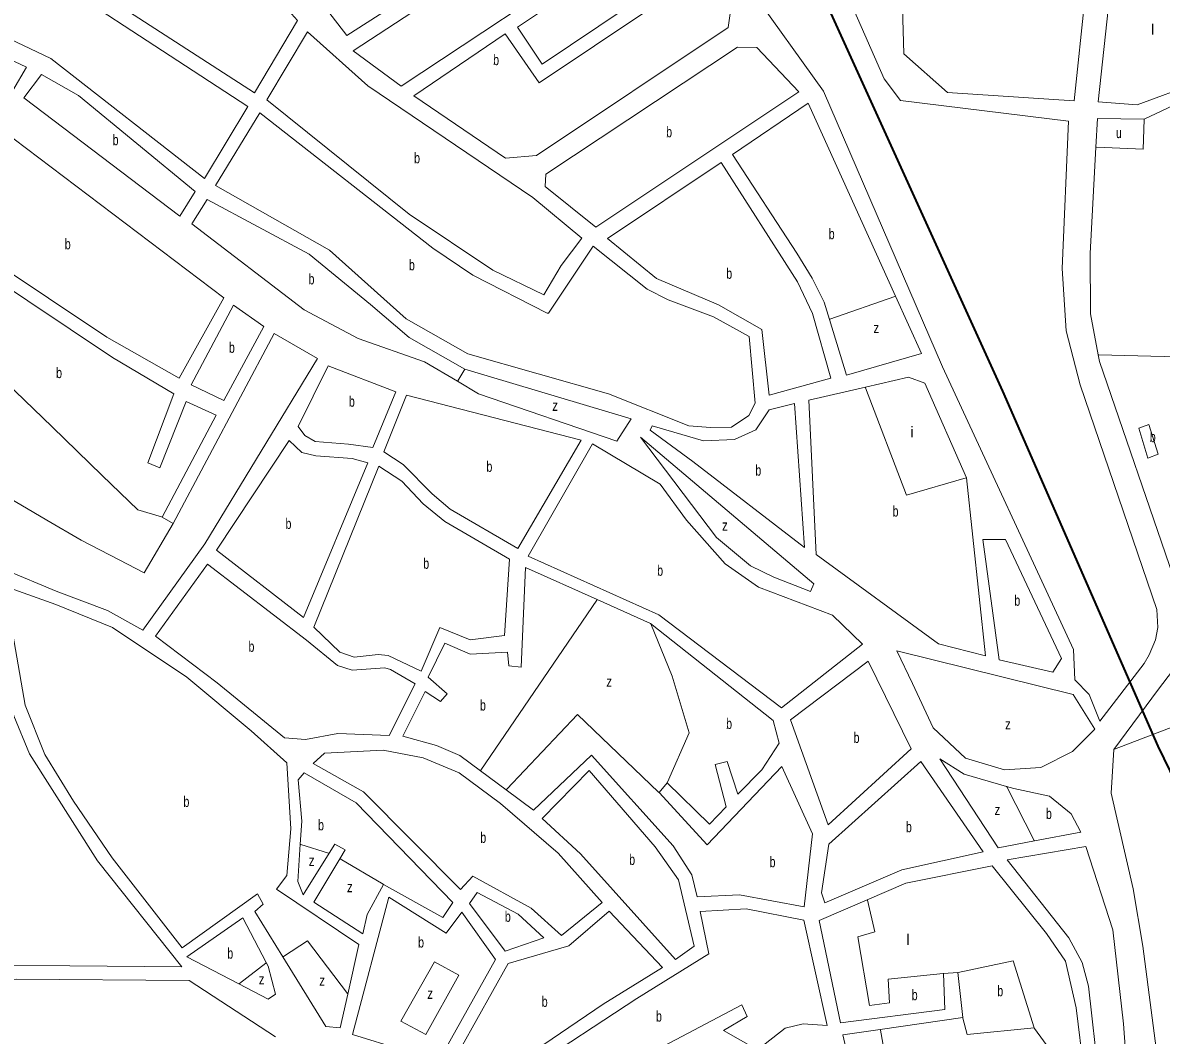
# Model space of a CAD drawing. Extents: x 639657 to 671642, y 222838 to 252123.
# Drawn here: x 648167 to 649239, y 232133 to 233086 of the extents above; entities that cross this region are included whole.
import ezdxf

# ---------------------------------------------------------------- set-up
doc = ezdxf.new("R2010")
doc.units = 0
doc.header["$LTSCALE"] = 4
for name, color, linetype, lineweight in [('1', 7, 'Continuous', 13), ('21', 7, 'Continuous', 13), ('57', 7, 'Continuous', 35)]:
    doc.layers.add(name, color=color, linetype=linetype, lineweight=lineweight)
doc.layers.add('7', color=7, linetype='Continuous')

msp = doc.modelspace()

# ---------------------------------------------------------------- linework, layer by layer
at = {"layer": '1'}
msp.add_line((648398.01, 232198), (648396.301, 232201.288), dxfattribs=at)
for points in [[(649149.42, 232796.25), (649162.7, 232745.53), (649234.9, 232533.79), (649235.74, 232517.04), (649233.58, 232505.44), (649227.55, 232491.05), (649222.82, 232482.89), (649181.25, 232428.84), (649171.15, 232453.78), (649157.62, 232467.77), (649156.35, 232496.16), (649033.16, 232762.48), (648921.04, 233022.17), (648851.52, 233119.17), (648833.54, 233184.3), (648705.42, 233567.34), (648641.96, 233707.52), (648569.71, 233868.76), (648512.26, 233999.25), (648433.24, 234174.14), (648378.3, 234266.73), (648325.37, 234321.82), (648301.67, 234334.15), (648271.66, 234336.15)], [(648410.85, 234277.57), (648411.45, 234275.57), (648414.86, 234264.21), (648539.54, 233999.64), (648604.08, 233855.17), (648722.62, 233578.92), (648824.9, 233360.7), (648844.86, 233337.47), (648978.2, 233033.69), (648993.58, 233013.129)], [(648225.054, 233203.292), (648248.4, 233188.4), (648255.07, 233200.42), (648062.83, 233327.86), (648149.35, 233433.42), (648226.41, 233333.22), (648312.95, 233263.5), (648312.48, 233220.11), (648394.74, 233169.08), (648405.91, 233157.03), (648408.65, 233107.4), (648425.61, 233088.68), (648385.14, 233020.4), (648212.53, 233132.292)], [(649177.692, 233210.382), (649156.94, 233013.02), (649037.7, 233020.93), (648996.49, 233057.3), (648995.45, 233100.91)], [(649222.88, 232995.73), (649266.95, 233016.51), (649288.86, 233018.41), (649700.501, 232988.195)], [(648835.25, 232962.36), (648906.42, 233010.59), (648988.767, 232828.86)], [(649149.42, 232796.25), (649145.61, 232855.12), (649151.76, 232993.9), (648993.58, 233013.129)], [(649179.602, 232773.657), (649172.43, 232812.33), (649172.05, 232869.05), (649177.403, 232969.313), (649178.84, 232996.23), (649222.88, 232995.73)], [(648926.536, 232807.069), (648921.49, 232823.44), (648910.34, 232845.8), (648895.97, 232869.46), (648835.25, 232962.36)], [(648326.13, 232897.12), (648340.56, 232919.89), (648436.58, 232868.61), (648494.56, 232821.24), (648530.86, 232790.03), (648583.27, 232760.29)], [(648545.23, 232767.22), (648482.93, 232789.23), (648432.02, 232816.17), (648326.13, 232897.12)], [(648988.767, 232828.86), (649013.19, 232774.96), (648942.69, 232754.66), (648926.536, 232807.069)], [(649696.519, 232781.063), (649672.36, 232773.13), (649516.76, 232732.54), (649486.67, 232722.7), (649454.65, 232710.29), (649413.37, 232686.72), (649387.35, 232664.84), (649358.11, 232634.81), (649254.42, 232501.75), (649256.81, 232531.83), (649250.18, 232565.35), (649180.76, 232767.41), (649179.602, 232773.657)], [(648583.27, 232760.29), (648739.977, 232713.536), (648726.344, 232692.457), (648596.211, 232737.095), (648576.458, 232748.767), (648545.23, 232767.22)], [(648960.414, 232743.281), (649001.01, 232752.63), (649016.48, 232747.02), (649055.72, 232657.97)], [(648914.05, 232585.72), (648907.3, 232731.05), (648960.414, 232743.281)], [(649055.72, 232657.97), (649073.63, 232490.25), (649029.16, 232501.49), (648914.05, 232585.72)], [(648707.754, 232543.291), (648640.27, 232573.4), (648636.33, 232479.66), (648624.72, 232480.96), (648623.44, 232493.65), (648588.2, 232491.76), (648564.35, 232502.11), (648548.64, 232470.09), (648566.68, 232454.59), (648560.23, 232447.28), (648545.84, 232456.55), (648524.96, 232414.64), (648556.54, 232405.78), (648578.67, 232396.51), (648598.137, 232382.016), (648622.254, 232364.061)], [(648169.29, 232443.92), (648149.82, 232555.98), (648198.16, 232538.71), (648251.66, 232516.93), (648321.69, 232470.17), (648382.05, 232419.56), (648415.76, 232389.41), (648419.37, 232327.46), (648415.69, 232283.37), (648406.01, 232270.48), (648483.55, 232218.33), (648473.05, 232171.684)], [(648879.1, 232408.15), (648873.53, 232429.24), (648758.21, 232520.78), (648707.754, 232543.291)], [(648148.401, 232478.275), (648158.54, 232433.82), (648173.55, 232397.89), (648237.53, 232297.15), (648316.77, 232197.46), (648035, 232199.74), (648013.55, 232259.79)], [(649194.31, 232402.14), (649236.25, 232458.85), (649249.595, 232476.12)], [(648411.921, 232206.703), (648385.58, 232249.43), (648393.53, 232256.52), (648387.95, 232266.2), (648317.21, 232215.1), (648251.29, 232299.93), (648214.79, 232353.32), (648187.95, 232397.44), (648169.29, 232443.92)], [(648773.77, 232370.66), (648813.71, 232331.68), (648829.41, 232348), (648818.91, 232387.8), (648830.3, 232390.59), (648840.17, 232360.03), (648862.96, 232382.8), (648879.1, 232408.15)], [(648622.254, 232364.061), (648647.83, 232345.02), (648702.67, 232396.78), (648779.32, 232311.29), (648796.92, 232283.96), (648802.06, 232263.3), (648842.03, 232265.18), (648902.62, 232253.92), (648910.62, 232322.73), (648881.87, 232386), (648811.34, 232312.11), (648766.25, 232361.42), (648773.77, 232370.66)], [(649435.192, 231967.793), (649290.77, 231943.33), (649292.43, 231931.86), (649328.02, 231936.28), (649345.19, 231853.16), (649266.36, 231847.82), (649249.9, 231999.94), (649221.67, 232216.71), (649212.68, 232270.71), (649191.78, 232361.07), (649194.31, 232402.14)], [(649085.3, 232309.38), (649030.5, 232393.21), (649053.55, 232378.67), (649093.294, 232367.255)], [(648426.5, 232373.48), (648432.09, 232379.92), (648480.85, 232351.69), (648572.12, 232258.01), (648562.44, 232243.82), (648506.8, 232274.87)], [(648428.275, 232312.776), (648429.69, 232334.55), (648426.5, 232373.48)], [(649093.294, 232367.255), (649100.17, 232365.28), (649133.9, 232358.14), (649154.3, 232341.55), (649163.18, 232324.3), (649119.701, 232315.97), (649085.3, 232309.38)], [(648455.454, 232304.409), (648430.93, 232265.29), (648426, 232277.77), (648428.275, 232312.776)], [(648465.543, 232299.222), (648470.51, 232307.61), (648460.84, 232313), (648455.454, 232304.409)], [(648506.8, 232274.87), (648491.31, 232246.71), (648487.21, 232228.43), (648441.24, 232258.18), (648465.543, 232299.222)], [(649164.269, 232079.164), (649166.15, 232099.77), (649158.89, 232158.72), (649148.82, 232202.61), (649131.01, 232228.67), (649079.7, 232292.4), (648998.47, 232276.16), (648962.185, 232260.501)], [(648962.185, 232260.501), (648917, 232241), (648936.92, 232144.6), (649035.34, 232157.16), (649034.07, 232191.15), (649047.4, 232191.99), (649052.09, 232149.61), (648974.463, 232138.318)], [(648396.301, 232201.288), (648374.4, 232243.42), (648321.5, 232206.92), (648370.508, 232181.218)], [(648473.05, 232171.684), (648465.88, 232139.83), (648452.34, 232141.14), (648411.921, 232206.703)], [(647873.27, 232058.69), (647842.52, 232171.87), (647876.67, 232179.48), (647902.85, 232191.15), (647914.22, 232197.19), (647927.75, 232198.51), (647998, 232191.36), (648045.09, 232184.46), (648160.73, 232185.61), (648323.64, 232184.54), (648405.05, 232131.52)], [(648370.508, 232181.218), (648397.98, 232166.81), (648404.87, 232171.53), (648398.01, 232198)], [(648974.463, 232138.318), (648939.28, 232133.2), (648951.326, 232079.88)]]:
    msp.add_lwpolyline(points, dxfattribs=at)
for points in [[(649287.22, 233318.98), (649213.75, 233328.11), (649179.71, 233011.91), (649216.45, 233009.06), (649272.55, 233030.03), (649362.14, 233026.03), (649369.76, 233128.72), (649279.1, 233137.23), (649274.98, 233105.01), (649261.02, 233106.53)], [(648444.58, 233110.54), (648706.86, 233280.09), (648734.76, 233242.88), (648472.26, 233074.4)], [(648000.52, 233144.9), (647974.42, 233156.59), (648019.66, 233245.64), (648064.01, 233219.58), (648130.37, 233169.87), (648379.11, 233007.52), (648338.21, 232939.88), (648193.45, 233052.89)], [(648478.05, 233060), (648523.35, 233026.84), (648715.12, 233153.75), (648746.66, 233108.58), (648801.48, 233145.24), (648741.62, 233232.56)], [(647964.35, 233144.11), (648000.93, 233125.13), (648170.66, 233044.54), (648157.74, 233022.64), (648069.45, 233078.41), (648001.8, 233105.29), (647920.77, 233131.33), (647929.3, 233156.48)], [(648632.98, 233082.33), (648712.96, 233136.14), (648736.13, 233101.3), (648656.15, 233047.49)], [(648535.37, 233017.59), (648621.37, 233075.9), (648653.34, 233029.87), (648808.56, 233134.06), (648833.45, 233097.5), (648831.07, 233082.03), (648650.91, 232961.34), (648621.69, 232959.02)], [(648491.96, 233026.92), (648435.06, 233077.92), (648396.95, 233013.94), (648530.96, 232906.09), (648609.78, 232853.54), (648657.69, 232830.27), (648673.83, 232857.76), (648693.41, 232883.73), (648647.46, 232921.84)], [(648658.83, 232932.33), (648659.7, 232943.93), (648839.86, 233063.54), (648858.13, 233063.09), (648897.83, 233021.56), (648706.49, 232893.8)], [(648168.05, 233015.75), (648184.63, 233037.86), (648219.43, 233018.05), (648329.39, 232927.64), (648314.96, 232904.45)], [(648553.07, 232874.04), (648390.28, 233001.48), (648348.52, 232933.2), (648455.71, 232872.45), (648528.08, 232807.66), (648586.07, 232774.69), (648718.42, 232736.9), (648794.04, 232706.91), (648814.45, 232705.17), (648834.43, 232705.57), (648850.56, 232716.73), (648856.59, 232728.32), (648851.06, 232791.1), (648817.34, 232809.63), (648774.59, 232825.38), (648755.04, 232835.72), (648704.15, 232876.2), (648662.18, 232813.06), (648660.89, 232813.07), (648590.87, 232848.84)], [(648356.38, 232827.45), (648135.36, 232994.3), (648068.43, 232897.04), (648136.1, 232863.85), (648246.09, 232790.41), (648314.4, 232751.84)], [(648717.65, 232883.25), (648824.5, 232954.86), (648896.37, 232842.6), (648910.74, 232812.71), (648927.87, 232751.89), (648869.84, 232735.86), (648862.81, 232797.53), (648822.01, 232820.79), (648763.6, 232845.59)], [(648308.7, 232614.9), (648403.63, 232793.85), (648444.44, 232770.15), (648338.34, 232595.73), (648280.25, 232514.52), (648246.95, 232533.06), (648198.6, 232551.18), (648150.47, 232571.24), (648130.92, 232576.86), (648100.19, 232590.87), (648076.14, 232618.43), (648045, 232647.06), (648031.05, 232673.31), (648028.29, 232712.22), (648028.99, 232785.96), (648063.9, 232882.64), (648131.58, 232851.39), (648251.66, 232771.27), (648309.23, 232737.01), (648284.67, 232671.91), (648296.27, 232667.16), (648320.83, 232729.9), (648349.19, 232716.97), (648298.17, 232620.93)], [(648393.96, 232800.31), (648365.61, 232820.56), (648325.57, 232745.37), (648356.29, 232730.72)], [(648426.33, 232706.12), (648454.54, 232763.26), (648518.34, 232738.88), (648496.81, 232686.46), (648473.6, 232689.72), (648442.44, 232692.12), (648432.77, 232697.72)], [(648507.12, 232682.36), (648528.44, 232735.65), (648692.81, 232693.29), (648633.19, 232591.47), (648569.61, 232628.32), (648552.43, 232642.74), (648525.16, 232670.3)], [(648903.1, 232592.18), (648893.76, 232727.84), (648869.69, 232721.86), (648857.21, 232703.17), (648837.22, 232693.96), (648807.99, 232692.71), (648759.65, 232706.96), (648757.72, 232702.88), (648798.09, 232673.16)], [(648820.38, 232601.54), (648748.653, 232696.177), (648911.88, 232558.2), (648908.87, 232550.89), (648874.28, 232564.27), (648852.37, 232575.05)], [(648431.34, 232526.37), (648349.51, 232589.69), (648417.94, 232693.02), (648429.97, 232681.6), (648442.86, 232678.58), (648477.24, 232675.95), (648492.07, 232672.06)], [(648881.49, 232441.27), (648957.6, 232501.16), (648929.48, 232528.5), (648859.88, 232555.04), (648828.31, 232577.02), (648792.03, 232617.91), (648767.13, 232651.92), (648703.55, 232690.05), (648643.07, 232584.14), (648765.95, 232528.72)], [(648441.01, 232517.11), (648502.38, 232668.82), (648523.86, 232654.82), (648544.04, 232633.51), (648564.45, 232616.71), (648625.45, 232581.37), (648620.66, 232509.35), (648588.21, 232505.31), (648559.85, 232516.96), (648542.2, 232475.69), (648511.05, 232490.57), (648501.81, 232491.44), (648479.02, 232489.11), (648465.49, 232493.86)], [(649086.3, 232486.36), (649071.14, 232599.91), (649092.41, 232599.88), (649145.17, 232487.79), (649136.78, 232474.9)], [(648292.06, 232508.92), (648341.12, 232576.59), (648434.12, 232505.08), (648463.33, 232481.17), (648477.3, 232476.64), (648507.81, 232478.96), (648513.4, 232477.45), (648536.6, 232463.87), (648512.06, 232415.3), (648463.71, 232417.09), (648433.4, 232411.54), (648413.42, 232413.07), (648350.06, 232464.76)], [(649004.63, 232464.33), (648990.083, 232494.986), (649155.89, 232453.8), (649176.44, 232421.04), (649155.42, 232400.04), (649125.54, 232385.24), (649091.37, 232382.92), (649054.64, 232393.73), (649024.37, 232422.37)], [(648925.45, 232331.1), (648889.86, 232430.07), (648963.18, 232485.24), (649003.51, 232402.61)], [(648671.22, 232304.55), (648712.45, 232258.04), (648674.18, 232226.9), (648645.61, 232252.53), (648590.84, 232282.72), (648579.22, 232270.26), (648487.74, 232362.22), (648440.48, 232388.94), (648451.02, 232398.61), (648506.25, 232401.33), (648544.07, 232394.19), (648577.8, 232379.95), (648616.89, 232351.08)], [(649012.74, 232390.77), (649071.33, 232305.74), (648994.61, 232288.64), (648922.17, 232257.55), (648918.96, 232267.02), (648925.87, 232312.82)], [(648762.56, 232310.24), (648700.29, 232382.37), (648656.2, 232337.05), (648692.07, 232303.88), (648781.6, 232204.39), (648799.23, 232216.84), (648784.45, 232279.24)], [(649232.038, 231829.653), (649214.54, 231993.69), (649203.35, 232143.82), (649193.32, 232232.24), (649167.98, 232310.59), (649093.89, 232298.19), (649152.06, 232224.77), (649164.5, 232201.52), (649170.5, 232179.14), (649180.11, 232092.44), (649175.15, 232064.48), (649162.26, 231969.89), (649154.98, 231825.2)], [(648633.57, 232246.96), (648594.91, 232267.44), (648587.59, 232257.13), (648621.3, 232212.13), (648657.63, 232224.56)], [(648477.48, 232133.79), (648511.74, 232262.82), (648565.65, 232229.19), (648580.5, 232248.75), (648612.05, 232204.18), (648554.39, 232100.99), (648524.32, 232119.1)], [(648681.26, 232217), (648719.32, 232249.64), (648769.35, 232196.88), (648713.67, 232162.1), (648633.26, 232107.56), (648601.22, 232069.74), (648565.13, 232094.96), (648624.09, 232200.51)], [(648812.98, 232209.51), (648804.84, 232249.32), (648848.04, 232252.06), (648902.61, 232241.44), (648924.46, 232142.04), (648901.68, 232143.79), (648884.92, 232139.72), (648858.9, 232119.32), (648826.9, 232137.43), (648849.25, 232150.74), (648844.11, 232161.5), (648669.13, 232069.22), (648641.17, 232039.57), (648611.1, 232062.84), (648642.07, 232099.59), (648745.26, 232167.65)]]:
    msp.add_lwpolyline(points, close=True, dxfattribs=at)
at = {"layer": '21'}
for points in [[(649222.88, 232995.73), (649222.865, 232995.23), (649222.013, 232967.285), (649177.903, 232969.29), (649177.403, 232969.313)], [(648926.536, 232807.069), (648927.036, 232807.244), (648988.267, 232828.685), (648988.767, 232828.86)], [(649697.531, 232833.671), (649697.35, 232833.17), (649684.414, 232797.218), (649668.561, 232786.644), (649290.713, 232796.337), (649290.713, 232770.783), (649180.101, 232773.644), (649179.602, 232773.657)], [(648308.7, 232614.9), (648281.495, 232568.32), (648257.947, 232580.72), (648222.005, 232599.319), (648189.782, 232617.918), (648147.644, 232642.717), (648119.138, 232676.195), (648091.872, 232712.153), (648086.915, 232749.351), (648110.463, 232789.029), (648129.053, 232770.43), (648160.037, 232739.432), (648194.739, 232705.954), (648241.835, 232660.076), (648275.298, 232627.837), (648297.67, 232621.081), (648298.17, 232620.93)], [(648583.27, 232760.29), (648576.754, 232749.267), (648576.458, 232748.767)], [(648960.414, 232743.281), (648960.604, 232742.781), (648999.003, 232641.618), (649055.22, 232657.826), (649055.72, 232657.97)], [(648707.754, 232543.291), (648707.414, 232542.791), (648598.477, 232382.516), (648598.137, 232382.016)], [(648773.77, 232370.66), (648773.991, 232371.16), (648794.591, 232417.668), (648778.479, 232470.985), (648758.414, 232520.28), (648758.21, 232520.78)], [(648622.254, 232364.061), (648622.726, 232364.561), (648689.245, 232435.027), (648765.75, 232361.898), (648766.25, 232361.42)], [(649194.31, 232402.14), (649194.81, 232402.332), (649271.201, 232431.694), (649271.307, 232431.735)], [(649093.294, 232367.255), (649093.551, 232366.755), (649119.444, 232316.47), (649119.701, 232315.97)], [(648455.454, 232304.409), (648454.954, 232304.563), (648428.775, 232312.622), (648428.275, 232312.776)], [(648506.8, 232274.87), (648506.3, 232275.165), (648466.043, 232298.927), (648465.543, 232299.222)], [(649034.07, 232191.15), (649033.57, 232191.099), (648981.733, 232185.799), (648982.973, 232163.48), (648964.382, 232161), (648953.228, 232225.477), (648969.34, 232230.437), (648962.304, 232260.001), (648962.185, 232260.501)], [(648411.921, 232206.703), (648412.421, 232207.027), (648435.176, 232221.757), (648472.672, 232172.185), (648473.05, 232171.684)], [(649119.303, 232139.921), (649099.473, 232203.158), (649047.9, 232192.097), (649047.4, 232191.99)], [(648396.301, 232201.288), (648395.801, 232200.899), (648371.008, 232181.607), (648370.508, 232181.218)], [(649052.09, 232149.61), (649052.216, 232149.11), (649056.095, 232133.722), (649119.303, 232139.921)], [(649119.303, 232139.921), (649119.665, 232139.421), (649144.967, 232104.463), (649145.329, 232103.963)], [(648951.326, 232079.88), (648951.826, 232079.963), (648984.212, 232085.364), (648974.555, 232137.818), (648974.463, 232138.318)]]:
    msp.add_lwpolyline(points, dxfattribs=at)
for points in [[(649217.731, 232704.739), (649226.417, 232676.497), (649236.106, 232680.022), (649227.298, 232708.22)], [(648554.625, 232202.217), (648577.703, 232189.519), (648546.719, 232133.721), (648523.171, 232146.121)]]:
    msp.add_lwpolyline(points, close=True, dxfattribs=at)
at = {"layer": '57'}
msp.add_lwpolyline([(649431.73, 232002.995), (649399.994, 232070.308), (649353.025, 232164.294), (649236.203, 232405.189), (649089.828, 232739.384), (648914.202, 233126.457), (648685.944, 233640.163), (648499.009, 234038.457), (648378.361, 234308.787), (648275.477, 234548.58), (648171.383, 234786.42), (648107.014, 234960.761), (648078.134, 235089.132), (648042.869, 235271.292), (648019.786, 235394.046), (648011.928, 235560.15), (648011.719, 235757.044), (648014.054, 235904.557)], dxfattribs=at)

# ---------------------------------------------------------------- texts
at = {"layer": '7'}
for s, p in [('l', (649229.5, 233075.23)), ('i', (649002.721, 232696.175)), ('l', (648999.086, 232218.037))]:
    msp.add_text(s, height=10, dxfattribs=at).set_placement(p)
for s, width, p in [('b', 0.75, (648609.915, 233046.54)), ('b', 0.75, (648772.811, 232978.67)), ('u', 0.7, (649196.471, 232977.859)), ('b', 0.75, (648251.689, 232971.155)), ('b', 0.75, (648535.52, 232954.095)), ('b', 0.75, (648925.885, 232882.625)), ('b', 0.75, (648206.625, 232873.07)), ('b', 0.75, (648530.607, 232853.325)), ('b', 0.75, (648436.109, 232840.09)), ('b', 0.75, (648829.372, 232845.36)), ('z', 0.8, (648968.017, 232794.129)), ('b', 0.75, (648361.148, 232775.64)), ('b', 0.75, (648198.457, 232751.831)), ('b', 0.75, (648474.082, 232724.86)), ('z', 0.8, (648665.616, 232720.976)), ('b', 0.75, (649228.179, 232691.477)), ('b', 0.75, (648603.615, 232663.56)), ('b', 0.75, (648856.786, 232660.01)), ('b', 0.75, (648986.006, 232621.44)), ('b', 0.75, (648414.416, 232609.695)), ('z', 0.8, (648825.493, 232608.142)), ('b', 0.75, (648544.081, 232572.255)), ('b', 0.75, (648764.336, 232565.66)), ('b', 0.75, (649100.651, 232537.405)), ('b', 0.75, (648379.574, 232494.065)), ('z', 0.8, (648716.511, 232461.066)), ('b', 0.75, (648597.533, 232438.747)), ('b', 0.75, (648829.293, 232421.388)), ('z', 0.8, (649091.956, 232420.911)), ('b', 0.75, (648949.266, 232408.17)), ('b', 0.75, (648318.335, 232347.905)), ('z', 0.8, (649082.041, 232340.315)), ('b', 0.75, (649130.376, 232336.595)), ('b', 0.75, (648445.091, 232325.912)), ('b', 0.75, (648998.573, 232324.16)), ('b', 0.75, (648597.823, 232314.115)), ('z', 0.8, (648436.416, 232292.434)), ('b', 0.75, (648737.992, 232293.38)), ('b', 0.75, (648870.192, 232291.194)), ('z', 0.8, (648472.357, 232267.635)), ('b', 0.75, (648620.93, 232239.785)), ('b', 0.75, (648539.283, 232215.558)), ('b', 0.75, (648359.627, 232205.115)), ('z', 0.8, (648389.32, 232180.839)), ('z', 0.8, (648446.33, 232179.599)), ('z', 0.8, (648547.958, 232167.2)), ('b', 0.75, (649004.042, 232165.96)), ('b', 0.75, (649084.6, 232169.68)), ('b', 0.75, (648655.702, 232159.69)), ('b', 0.75, (648763.261, 232145.815))]:
    msp.add_text(s, height=10, dxfattribs=dict(at, width=width)).set_placement(p)

doc.saveas('drawing.dxf')
